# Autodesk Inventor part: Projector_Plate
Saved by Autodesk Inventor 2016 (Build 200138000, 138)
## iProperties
Created: 2016-03
Part Number: Projector_Plate
Material: Generic
Document SubType Name: Modeling
Designer: bongo_000
Density: 1 g/cm^3
Appearance: Default
Author: bongo_000
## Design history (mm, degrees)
feature "SOLID1"
body "Solid1"
